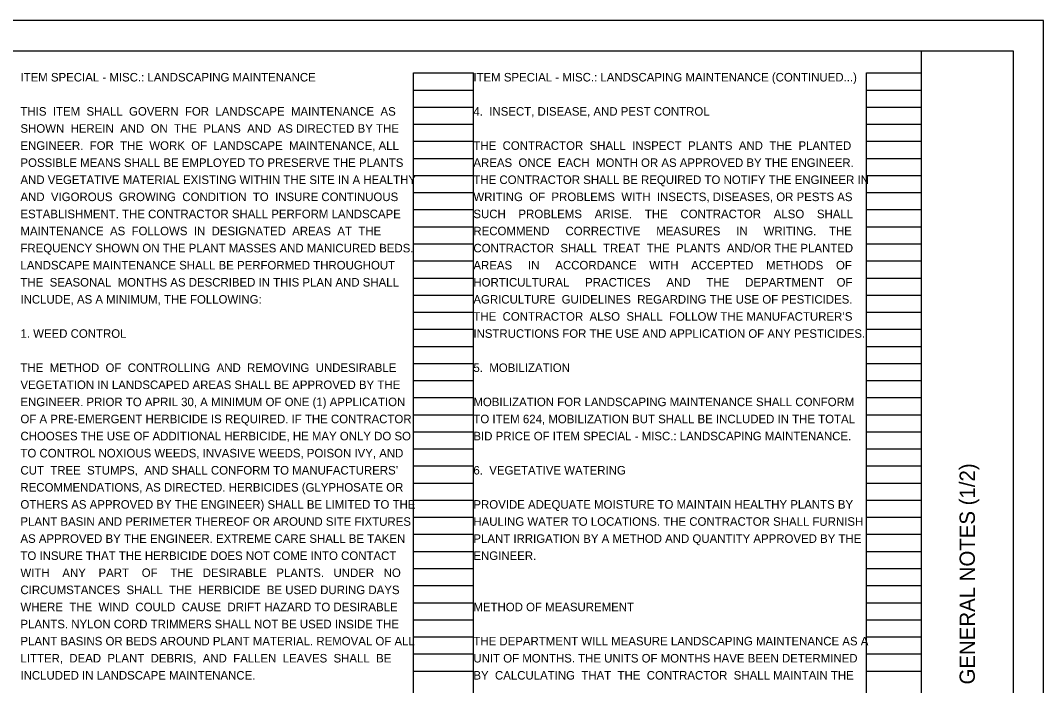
# Model space of a CAD drawing. Extents: x 0 to 34, y 0 to 22.
# Drawn here: x 17.24 to 34, y 11.1 to 22 of the extents above; entities that cross this region are included whole.
import ezdxf

# ---------------------------------------------------------------- set-up
doc = ezdxf.new("R2010")
doc.units = 0
for name, color, linetype in [('SH_Border', 7, 'Continuous'), ('SH_Cut_Line', 7, 'Continuous'), ('SH_Data', 7, 'Continuous'), ('SH_Text', 7, 'Continuous')]:
    doc.layers.add(name, color=color, linetype=linetype)

msp = doc.modelspace()

# ---------------------------------------------------------------- linework, layer by layer
at = {"layer": 'SH_Border'}
msp.add_line((32, 0.5), (32, 21.5), dxfattribs=at)
msp.add_lwpolyline([(1.5, 21.5), (33.5, 21.5), (33.5, 0.5), (1.5, 0.5)], close=True, dxfattribs=at)
at = {"layer": 'SH_Cut_Line'}
msp.add_lwpolyline([(0, 0), (34, 0), (34, 22), (0, 22)], close=True, dxfattribs=at)
at = {"layer": 'SH_Data'}
for p, q in [((23.68, 0.98), (23.68, 21.14)), ((23.68, 21.14), (24.66, 21.14)), ((24.66, 0.98), (24.66, 21.14)), ((31.1, 0.98), (31.1, 21.14)), ((31.1, 21.14), (32, 21.14)), ((32, 0.98), (32, 21.14)), ((23.68, 20.86), (24.66, 20.86)), ((31.1, 20.86), (32, 20.86)), ((23.68, 20.58), (24.66, 20.58)), ((31.1, 20.58), (32, 20.58)), ((23.68, 20.3), (24.66, 20.3)), ((31.1, 20.3), (32, 20.3)), ((23.68, 20.02), (24.66, 20.02)), ((31.1, 20.02), (32, 20.02)), ((23.68, 19.74), (24.66, 19.74)), ((31.1, 19.74), (32, 19.74)), ((23.68, 19.46), (24.66, 19.46)), ((31.1, 19.46), (32, 19.46)), ((23.68, 19.18), (24.66, 19.18)), ((31.1, 19.18), (32, 19.18)), ((23.68, 18.9), (24.66, 18.9)), ((31.1, 18.9), (32, 18.9)), ((23.68, 18.62), (24.66, 18.62)), ((31.1, 18.62), (32, 18.62)), ((23.68, 18.34), (24.66, 18.34)), ((31.1, 18.34), (32, 18.34)), ((23.68, 18.06), (24.66, 18.06)), ((31.1, 18.06), (32, 18.06)), ((23.68, 17.78), (24.66, 17.78)), ((31.1, 17.78), (32, 17.78)), ((23.68, 17.5), (24.66, 17.5)), ((31.1, 17.5), (32, 17.5)), ((23.68, 17.22), (24.66, 17.22)), ((31.1, 17.22), (32, 17.22)), ((23.68, 16.94), (24.66, 16.94)), ((31.1, 16.94), (32, 16.94)), ((23.68, 16.66), (24.66, 16.66)), ((31.1, 16.66), (32, 16.66)), ((23.68, 16.38), (24.66, 16.38)), ((31.1, 16.38), (32, 16.38)), ((23.68, 16.1), (24.66, 16.1)), ((31.1, 16.1), (32, 16.1)), ((23.68, 15.82), (24.66, 15.82)), ((31.1, 15.82), (32, 15.82)), ((23.68, 15.54), (24.66, 15.54)), ((31.1, 15.54), (32, 15.54)), ((23.68, 15.26), (24.66, 15.26)), ((31.1, 15.26), (32, 15.26)), ((23.68, 14.98), (24.66, 14.98)), ((31.1, 14.98), (32, 14.98)), ((23.68, 14.7), (24.66, 14.7)), ((31.1, 14.7), (32, 14.7)), ((23.68, 14.42), (24.66, 14.42)), ((31.1, 14.42), (32, 14.42)), ((23.68, 14.14), (24.66, 14.14)), ((31.1, 14.14), (32, 14.14)), ((23.68, 13.86), (24.66, 13.86)), ((31.1, 13.86), (32, 13.86)), ((23.68, 13.58), (24.66, 13.58)), ((31.1, 13.58), (32, 13.58)), ((23.68, 13.3), (24.66, 13.3)), ((31.1, 13.3), (32, 13.3)), ((23.68, 13.02), (24.66, 13.02)), ((31.1, 13.02), (32, 13.02)), ((23.68, 12.74), (24.66, 12.74)), ((31.1, 12.74), (32, 12.74)), ((23.68, 12.46), (24.66, 12.46)), ((31.1, 12.46), (32, 12.46)), ((23.68, 12.18), (24.66, 12.18)), ((31.1, 12.18), (32, 12.18)), ((23.68, 11.9), (24.66, 11.9)), ((31.1, 11.9), (32, 11.9)), ((23.68, 11.62), (24.66, 11.62)), ((31.1, 11.62), (32, 11.62)), ((23.68, 11.34), (24.66, 11.34)), ((31.1, 11.34), (32, 11.34))]:
    msp.add_line(p, q, dxfattribs=at)

# ---------------------------------------------------------------- texts
msp.add_text('GENERAL NOTES (1/2)', height=0.25, rotation=90, dxfattribs=at).set_placement((32.875, 11.12))
at = {"layer": 'SH_Text'}
for s, p in [('ITEM SPECIAL - MISC.: LANDSCAPING MAINTENANCE', (17.24, 21)), ('ITEM SPECIAL - MISC.: LANDSCAPING MAINTENANCE (CONTINUED...)', (24.66, 21)), ('THIS  ITEM  SHALL  GOVERN  FOR  LANDSCAPE  MAINTENANCE  AS', (17.24, 20.44)), ('4.  INSECT, DISEASE, AND PEST CONTROL', (24.66, 20.44)), ('SHOWN  HEREIN  AND  ON  THE  PLANS  AND  AS DIRECTED BY THE', (17.24, 20.16)), ('ENGINEER.  FOR  THE  WORK  OF  LANDSCAPE  MAINTENANCE, ALL', (17.24, 19.88)), ('THE  CONTRACTOR  SHALL  INSPECT  PLANTS  AND  THE  PLANTED', (24.66, 19.88)), ('POSSIBLE MEANS SHALL BE EMPLOYED TO PRESERVE THE PLANTS', (17.24, 19.6)), ('AREAS  ONCE  EACH  MONTH OR AS APPROVED BY THE ENGINEER.', (24.66, 19.6)), ('AND VEGETATIVE MATERIAL EXISTING WITHIN THE SITE IN A HEALTHY', (17.24, 19.32)), ('THE CONTRACTOR SHALL BE REQUIRED TO NOTIFY THE ENGINEER IN', (24.66, 19.32)), ('AND  VIGOROUS  GROWING  CONDITION  TO  INSURE CONTINUOUS', (17.24, 19.04)), ('WRITING  OF  PROBLEMS  WITH  INSECTS, DISEASES, OR PESTS AS', (24.66, 19.04)), ('ESTABLISHMENT. THE CONTRACTOR SHALL PERFORM LANDSCAPE', (17.24, 18.76)), ('SUCH    PROBLEMS    ARISE.    THE    CONTRACTOR    ALSO    SHALL', (24.66, 18.76)), ('MAINTENANCE  AS  FOLLOWS  IN  DESIGNATED  AREAS  AT  THE', (17.24, 18.48)), ('RECOMMEND     CORRECTIVE     MEASURES     IN     WRITING.    THE', (24.66, 18.48)), ('FREQUENCY SHOWN ON THE PLANT MASSES AND MANICURED BEDS.', (17.24, 18.2)), ('CONTRACTOR  SHALL  TREAT  THE  PLANTS  AND/OR THE PLANTED', (24.66, 18.2)), ('LANDSCAPE MAINTENANCE SHALL BE PERFORMED THROUGHOUT', (17.24, 17.92)), ('AREAS     IN     ACCORDANCE    WITH    ACCEPTED    METHODS    OF', (24.66, 17.92)), ('THE  SEASONAL  MONTHS AS DESCRIBED IN THIS PLAN AND SHALL', (17.24, 17.64)), ('HORTICULTURAL     PRACTICES     AND     THE     DEPARTMENT    OF', (24.66, 17.64)), ('INCLUDE, AS A MINIMUM, THE FOLLOWING:', (17.24, 17.36)), ('AGRICULTURE  GUIDELINES  REGARDING THE USE OF PESTICIDES.', (24.66, 17.36)), ('THE  CONTRACTOR  ALSO  SHALL  FOLLOW THE MANUFACTURER’S', (24.66, 17.08)), ('1. WEED CONTROL', (17.24, 16.8)), ('INSTRUCTIONS FOR THE USE AND APPLICATION OF ANY PESTICIDES.', (24.66, 16.8)), ('THE  METHOD  OF  CONTROLLING  AND  REMOVING  UNDESIRABLE', (17.24, 16.24)), ('5.  MOBILIZATION', (24.66, 16.24)), ('VEGETATION IN LANDSCAPED AREAS SHALL BE APPROVED BY THE', (17.24, 15.96)), ('ENGINEER. PRIOR TO APRIL 30, A MINIMUM OF ONE (1) APPLICATION', (17.24, 15.68)), ('MOBILIZATION FOR LANDSCAPING MAINTENANCE SHALL CONFORM', (24.66, 15.68)), ('OF A PRE-EMERGENT HERBICIDE IS REQUIRED. IF THE CONTRACTOR', (17.24, 15.4)), ('TO ITEM 624, MOBILIZATION BUT SHALL BE INCLUDED IN THE TOTAL', (24.66, 15.4)), ('CHOOSES THE USE OF ADDITIONAL HERBICIDE, HE MAY ONLY DO SO', (17.24, 15.12)), ('BID PRICE OF ITEM SPECIAL - MISC.: LANDSCAPING MAINTENANCE.', (24.66, 15.12)), ('TO CONTROL NOXIOUS WEEDS, INVASIVE WEEDS, POISON IVY, AND', (17.24, 14.84)), ('CUT  TREE  STUMPS,  AND SHALL CONFORM TO MANUFACTURERS’', (17.24, 14.56)), ('6.  VEGETATIVE WATERING', (24.66, 14.56)), ('RECOMMENDATIONS, AS DIRECTED. HERBICIDES (GLYPHOSATE OR', (17.24, 14.28)), ('OTHERS AS APPROVED BY THE ENGINEER) SHALL BE LIMITED TO THE', (17.24, 14)), ('PROVIDE ADEQUATE MOISTURE TO MAINTAIN HEALTHY PLANTS BY', (24.66, 14)), ('PLANT BASIN AND PERIMETER THEREOF OR AROUND SITE FIXTURES', (17.24, 13.72)), ('HAULING WATER TO LOCATIONS. THE CONTRACTOR SHALL FURNISH', (24.66, 13.72)), ('AS APPROVED BY THE ENGINEER. EXTREME CARE SHALL BE TAKEN', (17.24, 13.44)), ('PLANT IRRIGATION BY A METHOD AND QUANTITY APPROVED BY THE', (24.66, 13.44)), ('TO INSURE THAT THE HERBICIDE DOES NOT COME INTO CONTACT', (17.24, 13.16)), ('ENGINEER.', (24.66, 13.16)), ('WITH    ANY    PART    OF    THE   DESIRABLE   PLANTS.   UNDER   NO', (17.24, 12.88)), ('CIRCUMSTANCES  SHALL  THE  HERBICIDE  BE USED DURING DAYS', (17.24, 12.6)), ('WHERE  THE  WIND  COULD  CAUSE  DRIFT HAZARD TO DESIRABLE', (17.24, 12.32)), ('METHOD OF MEASUREMENT', (24.66, 12.32)), ('PLANTS. NYLON CORD TRIMMERS SHALL NOT BE USED INSIDE THE', (17.24, 12.04)), ('PLANT BASINS OR BEDS AROUND PLANT MATERIAL. REMOVAL OF ALL', (17.24, 11.76)), ('THE DEPARTMENT WILL MEASURE LANDSCAPING MAINTENANCE AS A', (24.66, 11.76)), ('LITTER,  DEAD  PLANT  DEBRIS,  AND  FALLEN  LEAVES  SHALL  BE', (17.24, 11.48)), ('UNIT OF MONTHS. THE UNITS OF MONTHS HAVE BEEN DETERMINED', (24.66, 11.48)), ('INCLUDED IN LANDSCAPE MAINTENANCE.', (17.24, 11.2)), ('BY  CALCULATING  THAT  THE  CONTRACTOR  SHALL MAINTAIN THE', (24.66, 11.2))]:
    msp.add_text(s, height=0.14, dxfattribs=at).set_placement(p)

doc.saveas('drawing.dxf')
